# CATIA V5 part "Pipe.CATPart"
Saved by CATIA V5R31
Part number: Pipe
Bounding box of the stored display mesh (mm): x -50 to 50, y 0 to 150, z -50 to 50
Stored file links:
  D:\PROJECTS\Project 2021\US EDITION\CATIA V5 6R 2021\Resources\Part Files\c12_catia_v5_6r2021_prt\c12_catia_v5-6r2021 figr_12-44\Pipe.CATPart
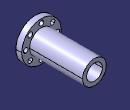
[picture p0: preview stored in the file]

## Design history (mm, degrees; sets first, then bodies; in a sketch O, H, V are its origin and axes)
Body1 (main body)
  Sketch1 on zx-plane, origin (0, 0, 0), H (-1, 0, 0), V (0, 0, 1)
    circle A1 centre (0, 0) radius 50
    point P1 (0, -50)
    circle A2 centre (0, 0) radius 30
    point P2 (0, -30)
    radius A1 = 50
    radius A2 = 30
    coincidence: A1 P1, P1 V, A2 P2, P2 V
  MultiPad1: profile Sketch1, domains (length 150; length 15)
  Sketch2 on face of MultiPad1, origin (0, 150, 0), H (-1, 0, 0), V (0, 0, 1)
    circle A1 centre (0, 0) radius 20
    point P1 (0, -20)
    radius A1 = 20
    coincidence: A1 P1, P1 V
  Pocket1: profile Sketch2, direction (0, -1, 0), through (limit type 3)
  Sketch3 on face of MultiPad1, origin (0, 0, 0), H (1, 0, 0), V (0, 0, 1)
    circle A1 centre (0, -40) radius 6
    point P1 (0, -40)
    radius A1 = 6
    distance H P1 = 40
    coincidence: P1 V
  Pocket2: profile Sketch3, direction (0, 1, 0), through (limit type 3)
  CircPattern1: of Pocket2, instances 8, angular step 45, axis from face of MultiPad1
